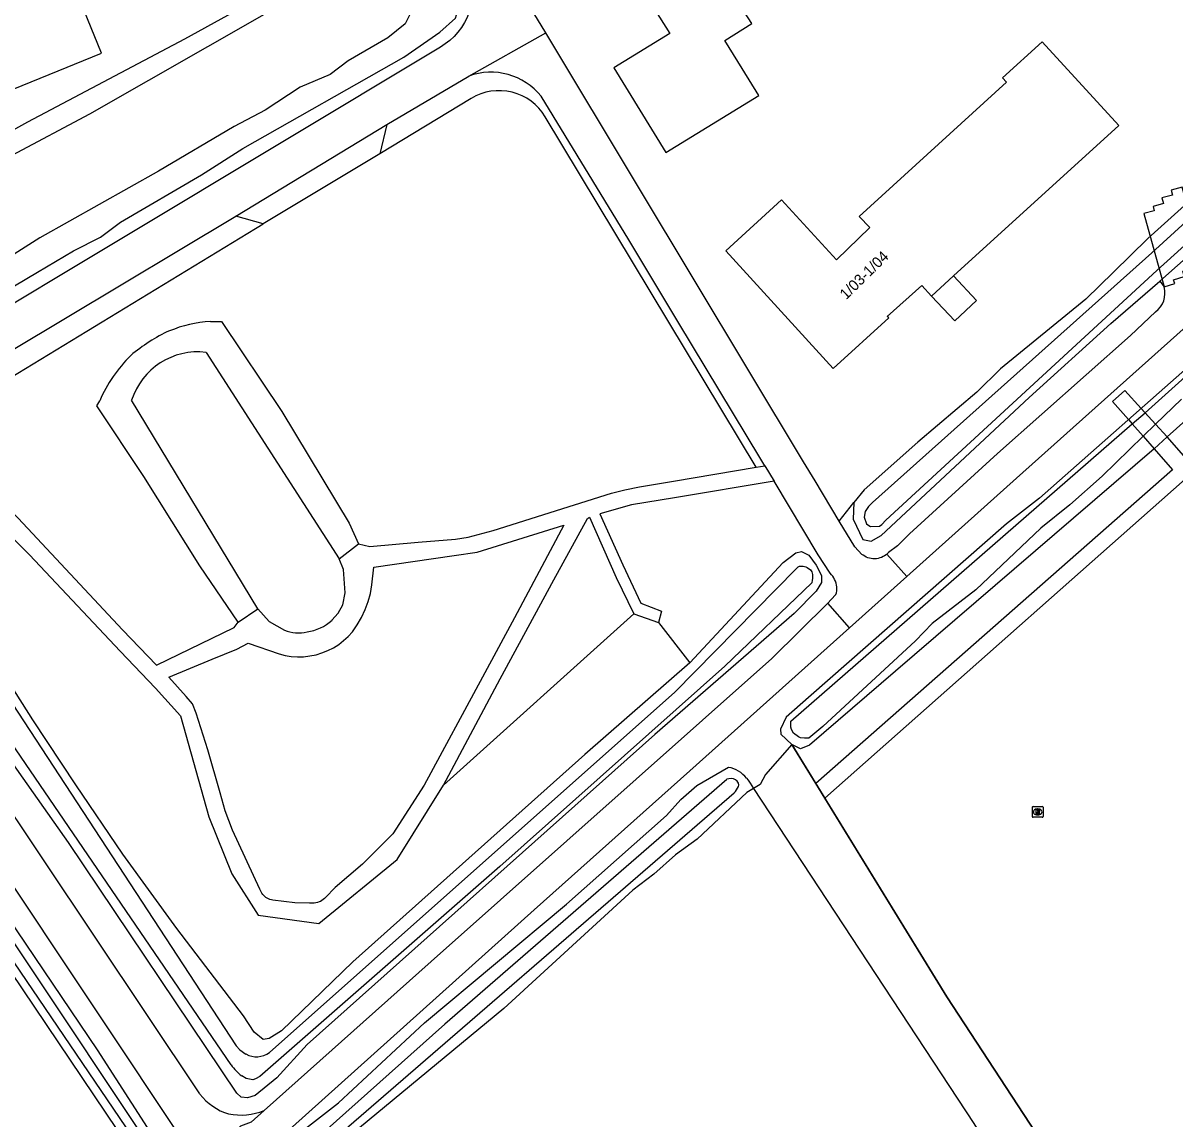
# Model space of a CAD drawing. Extents: x 162791 to 163827, y 385795 to 386523.
# Drawn here: x 163263.1 to 163370.1, y 386171.4 to 386273.1 of the extents above; entities that cross this region are included whole.
import ezdxf

# ---------------------------------------------------------------- set-up
doc = ezdxf.new("R2010")
doc.units = 0
for name, color, linetype in [('IMGEO_Dek', 7, 'Continuous'), ('IMGEO_Erf', 7, 'Continuous'), ('IMGEO_Gemengd_bos', 7, 'Continuous'), ('IMGEO_Grasland_overig', 7, 'Continuous'), ('IMGEO_Groenvoorziening', 7, 'Continuous'), ('IMGEO_Hek', 7, 'Continuous'), ('IMGEO_Meer_plas_ven_vijver', 7, 'Continuous'), ('IMGEO_Pand', 7, 'Continuous'), ('IMGEO_Pand_nummerreeks', 7, 'Continuous'), ('IMGEO_Parkeervlak_open', 7, 'Continuous'), ('IMGEO_Rijbaan_lokaal_gesloten', 7, 'Continuous'), ('IMGEO_Rijbaan_lokaal_onverhard', 7, 'Continuous'), ('IMGEO_Rijbaan_lokaal_open', 7, 'Continuous'), ('IMGEO_Rioolput', 7, 'Continuous'), ('IMGEO_Voetpad_halfverhard', 7, 'Continuous'), ('IMGEO_Voetpad_open', 7, 'Continuous'), ('IMGEO_Waterloop', 7, 'Continuous'), ('IMGEO_Woonerf_open', 7, 'Continuous')]:
    doc.layers.add(name, color=color, linetype=linetype)

msp = doc.modelspace()

# ---------------------------------------------------------------- linework, layer by layer
at = {"layer": 'IMGEO_Dek'}
for points in [[(163372.63, 386251.07), (163370.76, 386257.9), (163369.75, 386257.63), (163369.88, 386257.16), (163368.89, 386256.9), (163369.03, 386256.37), (163368.06, 386256.11), (163368.17, 386255.69), (163367.22, 386255.44), (163369.08, 386248.63), (163370.08, 386248.94), (163370.02, 386249.12), (163369.96, 386249.3), (163370.96, 386249.61), (163370.82, 386250.11), (163371.79, 386250.39), (163371.73, 386250.6), (163371.68, 386250.82)], [(163364.29, 386237.99), (163365.77, 386236.32), (163366.11, 386235.94), (163367.14, 386234.78), (163368.17, 386233.62), (163369.37, 386234.71), (163368.29, 386235.9), (163366.95, 386237.36), (163365.44, 386239.02)]]:
    msp.add_lwpolyline(points, close=True, dxfattribs=at)
at = {"layer": 'IMGEO_Erf'}
for points in [[(163358.27, 386329.73), (163369.6, 386309.18), (163388.13, 386275.57), (163388.75, 386273.87), (163388.79, 386272.87), (163388.39, 386271.95), (163377.29, 386261.58), (163375.71, 386260.44), (163370.68, 386255.93), (163367.59, 386253.14), (163364.39, 386250), (163361.83, 386247.49), (163353.89, 386241.04), (163351.71, 386238.86), (163346.21, 386234.23), (163341.23, 386229.79), (163340.29, 386228.61)], [(163276.83, 386311.46), (163279.76, 386304.64), (163280.52, 386303.16), (163282.08, 386299.04), (163282.71, 386297.57), (163284.13, 386298.22), (163285.26, 386295.57), (163283.84, 386294.94), (163285.21, 386290.76), (163289.29, 386279.83), (163289.57, 386278.55), (163289.29, 386277.99), (163288.89, 386277.59), (163278.14, 386271.64), (163263.57, 386263.94), (163238.52, 386250), (163202.05, 386229.7), (163201.46, 386229.64), (163200.89, 386229.9), (163200.49, 386230.52), (163192.64, 386244.3), (163191.66, 386246.6), (163189.98, 386249.35)], [(163274.97, 386170.16), (163270.07, 386177.82), (163239.23, 386223.44), (163238.43, 386224.34), (163237.21, 386225.02), (163236.42, 386225.12), (163236.06, 386224.76), (163236.06, 386224.12), (163236.48, 386222.54), (163248.69, 386204.78), (163271.93, 386170.32)]]:
    msp.add_lwpolyline(points, dxfattribs=at)
at = {"layer": 'IMGEO_Gemengd_bos'}
for points in [[(163304.75, 386266.14), (163296.27, 386260.98)], [(163331.22, 386231.89), (163311.63, 386264.44)], [(163254.1, 386235.44), (163285.45, 386254.48)], [(163280.54, 386245.44), (163281.58, 386245.44), (163287.17, 386237.08), (163293.43, 386226.72), (163294.29, 386224.79)], [(163283.13, 386217.51), (163279.55, 386222.75), (163274.35, 386231.03), (163270, 386237.61), (163270.26, 386238.07)], [(163325.04, 386213.73), (163315.3, 386205.22), (163293.77, 386185.98), (163287.15, 386179.57), (163285.99, 386178.87), (163285.43, 386178.77), (163284.59, 386179.47), (163283.61, 386180.97), (163277.41, 386189.09), (163272.42, 386195.99), (163268.06, 386202.41), (163264.06, 386208.45), (163254.95, 386222.79), (163250.27, 386230.43), (163248.69, 386232.43)], [(163302.17, 386202.38), (163319.84, 386218.29)], [(163322.14, 386217.49), (163325.04, 386213.73)]]:
    msp.add_lwpolyline(points, dxfattribs=at)
for centre, radius, start, end in [((163307.35, 386261.86), 5, 31.0344, 121.2892), ((163281.37, 386233.13), 12.33, 93.9007, 112.0819), ((163283.46, 386230.07), 15.98, 114.8683, 130.2264), ((163282.31, 386232.89), 13.11, 134.3562, 156.7334)]:
    msp.add_arc(centre, radius, start, end, dxfattribs=at)
at = {"layer": 'IMGEO_Grasland_overig'}
for points in [[(163334.51, 386206.17), (163332.07, 386203.39), (163331.59, 386202.45), (163330.97, 386202.08)], [(163336.75, 386202.54), (163334.51, 386206.17)], [(163330.97, 386202.08), (163351.42, 386170.99), (163365.11, 386149)], [(163362.1, 386162.58), (163348.93, 386182.75), (163337.58, 386201.19)]]:
    msp.add_lwpolyline(points, dxfattribs=at)
at = {"layer": 'IMGEO_Groenvoorziening'}
for points in [[(163368.7, 386249.16), (163371.96, 386252.09), (163377.03, 386256.71), (163385.29, 386263.34), (163391.11, 386268.71), (163392.33, 386269.57), (163393.55, 386270.85), (163394.31, 386272.69), (163394.11, 386273.91), (163392.21, 386278.19), (163380.4, 386298.93), (163365.93, 386326.24), (163364.85, 386327.62), (163362.85, 386330.8)], [(163252.47, 386242.88), (163264.5, 386250), (163267.84, 386251.98), (163270.34, 386253.26), (163272.2, 386254.66), (163279.7, 386259.03), (163283.55, 386261.5), (163298.51, 386269.95), (163301.83, 386272.3), (163303.3, 386273.58), (163303.68, 386274.82), (163303.11, 386277.82), (163302.56, 386279.48), (163300.7, 386283.62), (163296.46, 386294.57), (163295.4, 386296.91), (163293.61, 386299.37), (163293.55, 386299.51)], [(163427.28, 386208.26), (163414.75, 386232.44), (163403.01, 386252.5), (163398.12, 386260.39), (163369.37, 386234.71)], [(163340.29, 386228.61), (163340.21, 386227.08), (163341.13, 386225.2), (163341.89, 386225.04), (163342.83, 386225.55), (163356.55, 386238.38), (163364.15, 386245.23), (163368.7, 386249.16)], [(163368.7, 386249.16), (163369.08, 386248.63)], [(163372.59, 386242.33), (163357.51, 386229.03), (163354.47, 386226.65), (163336.07, 386210.51), (163333.99, 386208.69), (163333.47, 386207.59), (163333.51, 386207.13), (163334.51, 386206.17)], [(163368.17, 386233.62), (163344.16, 386212.98), (163336.15, 386206.1), (163335.32, 386205.75), (163334.51, 386206.17)], [(163338.93, 386226.9), (163340.29, 386228.61)], [(163325.04, 386213.73), (163333.73, 386223.04), (163334.91, 386223.94), (163335.43, 386224.08), (163336.11, 386223.72), (163336.79, 386222.82), (163337.29, 386221.84), (163337.29, 386221.2), (163336.79, 386220.4), (163334.73, 386218.32), (163321.8, 386207.09), (163289.51, 386178.31), (163286.71, 386175.23), (163284.71, 386173.57), (163283.97, 386173.37), (163283.41, 386173.43), (163282.99, 386173.79), (163267.36, 386197.05), (163261.24, 386205.77)], [(163287.36, 386166.66), (163287.39, 386168.29), (163287.86, 386169.13), (163288.55, 386169.85), (163292.44, 386172.89), (163300.42, 386180.32), (163313.6, 386191.33), (163322.88, 386199.58), (163324.21, 386201.04), (163325.71, 386202.34), (163328.64, 386204.04)], [(163330.33, 386203.03), (163330.48, 386202.84), (163330.67, 386202.56), (163330.97, 386202.08)], [(163330.97, 386202.08), (163330.35, 386201.71), (163325.73, 386197.38), (163323.73, 386195.92), (163321.71, 386194.12), (163319.76, 386192.64), (163307.78, 386181.66), (163290.44, 386167.33), (163290.58, 386166.67), (163292.7, 386163.19), (163298.6, 386154.45), (163302.55, 386148.89), (163315.83, 386127.93), (163319.34, 386122.66), (163322.46, 386118.35), (163322.79, 386117.68), (163363.42, 386149.31), (163364.28, 386149.43), (163365.11, 386149)]]:
    msp.add_lwpolyline(points, dxfattribs=at)
msp.add_arc((163328.15, 386201.32), 2.76, 38.0778, 79.7949, dxfattribs=at)
at = {"layer": 'IMGEO_Hek'}
for points in [[(163334.51, 386206.17), (163348.93, 386182.75), (163362.1, 386162.58)], [(163330.97, 386202.08), (163351.42, 386170.99), (163365.11, 386149)]]:
    msp.add_lwpolyline(points, dxfattribs=at)
at = {"layer": 'IMGEO_Meer_plas_ven_vijver'}
for points in [[(163280.15, 386242.56), (163292.5, 386223.4)], [(163284.93, 386218.74), (163273.23, 386238.11)]]:
    msp.add_lwpolyline(points, dxfattribs=at)
msp.add_arc((163279.38, 386236.15), 6.46, 83.1741, 162.3256, dxfattribs=at)
at = {"layer": 'IMGEO_Pand'}
for points in [[(163254.14, 386263.73), (163270.42, 386270.34), (163265.9, 386281.46), (163266.76, 386281.81), (163267.23, 386280.63), (163270.52, 386281.97), (163261.4, 386304.44), (163259.5, 386303.66), (163241.01, 386296.16)], [(163329.9, 386268.92), (163328.29, 386271.51), (163330.8, 386273.08), (163329.11, 386275.76), (163328.39, 386275.32), (163326.63, 386278.14), (163325.9, 386277.68), (163324.46, 386279.96), (163321.94, 386278.37), (163323.55, 386275.8), (163321.65, 386274.6), (163323.19, 386272.15), (163318, 386268.98), (163322.83, 386261.11), (163331.47, 386266.4), (163329.9, 386268.92)], [(163349.55, 386249.66), (163364.89, 386263.61), (163357.78, 386271.4), (163354.07, 386268.04), (163354.47, 386267.65), (163340.77, 386255.18), (163341.77, 386254.14), (163338.68, 386251.14), (163333.56, 386256.73), (163328.4, 386252), (163338.35, 386241.07), (163343.52, 386245.77), (163343.39, 386245.89), (163346.59, 386248.77), (163347.5, 386247.79)], [(163349.55, 386249.66), (163347.5, 386247.79)], [(163347.5, 386247.79), (163349.67, 386245.49), (163351.68, 386247.37), (163349.55, 386249.66)]]:
    msp.add_lwpolyline(points, dxfattribs=at)
at = {"layer": 'IMGEO_Parkeervlak_open'}
for points in [[(163282.9, 386255.22), (163296.91, 386263.73)], [(163296.91, 386263.73), (163296.27, 386260.98)], [(163296.27, 386260.98), (163285.45, 386254.48)], [(163285.45, 386254.48), (163282.9, 386255.22)]]:
    msp.add_lwpolyline(points, dxfattribs=at)
at = {"layer": 'IMGEO_Rijbaan_lokaal_gesloten'}
for points in [[(163369.08, 386248.63), (163370.08, 386248.94), (163370.02, 386249.12), (163369.96, 386249.3), (163370.96, 386249.61), (163370.82, 386250.11), (163371.79, 386250.39), (163371.73, 386250.6), (163371.68, 386250.82), (163372.63, 386251.07), (163373.14, 386251.61), (163373.59, 386251.78), (163375.27, 386252.83), (163375.62, 386252.47)], [(163377.43, 386250.6), (163374.94, 386248.38), (163355.39, 386230.89), (163345.19, 386221.76)], [(163368.3, 386246.33), (163365.96, 386244.13), (163353.63, 386233.16), (163345.45, 386225.73), (163344.35, 386224.61), (163343.51, 386223.98), (163343.39, 386223.87), (163343.34, 386223.83)], [(163345.19, 386221.76), (163343.34, 386223.83)], [(163337.86, 386219.29), (163332.67, 386214.15), (163301.05, 386186.01), (163285.54, 386172.19)], [(163339.87, 386217), (163337.86, 386219.29)], [(163286.36, 386169.05), (163288.16, 386170.66), (163310.61, 386190.82), (163325.04, 386203.73), (163339.87, 386217)], [(163285.54, 386172.19), (163284.33, 386171.11), (163283.34, 386170.74), (163279.05, 386166.85)]]:
    msp.add_lwpolyline(points, dxfattribs=at)
msp.add_arc((163367, 386248.06), 2.17, 306.9795, 15.362, dxfattribs=at)
at = {"layer": 'IMGEO_Rijbaan_lokaal_onverhard'}
for points in [[(163279.57, 386173.72), (163245.44, 386224.72)], [(163242.34, 386222.83), (163278.57, 386168.48)]]:
    msp.add_lwpolyline(points, dxfattribs=at)
for centre, radius, start, end in [((163283.65, 386176.76), 5.09, 216.7808, 253.8244), ((163283.37, 386177.46), 5.7, 258.3962, 292.3079)]:
    msp.add_arc(centre, radius, start, end, dxfattribs=at)
at = {"layer": 'IMGEO_Rijbaan_lokaal_open'}
for points in [[(163304.52, 386268.21), (163311.68, 386272.21)], [(163338.93, 386226.9), (163336.68, 386230.65), (163335.62, 386232.4), (163320.29, 386257.9), (163311.68, 386272.21)], [(163332.02, 386232.02), (163331.64, 386232.65), (163323.95, 386245.43), (163319.39, 386253.02), (163311.24, 386266.34)], [(163332.02, 386232.02), (163332.87, 386230.6)], [(163337.86, 386219.29), (163338.18, 386219.61), (163338.62, 386220.08), (163338.66, 386220.25), (163338.69, 386220.43), (163338.7, 386220.61), (163338.69, 386220.79), (163338.67, 386220.96), (163338.63, 386221.14), (163338.57, 386221.31), (163338.5, 386221.47), (163338.42, 386221.63), (163338.33, 386221.78), (163338.21, 386221.92), (163338.09, 386222.05), (163336.98, 386223.76), (163332.87, 386230.6)], [(163343.34, 386223.83), (163343.27, 386223.77), (163343.14, 386223.68), (163342.99, 386223.6), (163342.85, 386223.53), (163342.7, 386223.48), (163342.54, 386223.44), (163342.38, 386223.41), (163342.22, 386223.4), (163342.06, 386223.41), (163341.9, 386223.42), (163341.74, 386223.45), (163341.58, 386223.5), (163341.43, 386223.56), (163341.29, 386223.63), (163341.15, 386223.72), (163341.02, 386223.81), (163340.37, 386224.5), (163338.93, 386226.9)], [(163339.87, 386217), (163345.19, 386221.76)]]:
    msp.add_lwpolyline(points, dxfattribs=at)
msp.add_arc((163306.57, 386262.57), 6, 38.8826, 109.9355, dxfattribs=at)
at = {"layer": 'IMGEO_Rioolput'}
for p, q in [((163356.86, 386199.48), (163356.86, 386200.33)), ((163356.93, 386200.41), (163357.78, 386200.41)), ((163357.35, 386200.18), (163357.37, 386200.18)), ((163357.86, 386200.33), (163357.86, 386199.48)), ((163357.78, 386199.4), (163356.93, 386199.4)), ((163357.37, 386199.63), (163357.34, 386199.63))]:
    msp.add_line(p, q, dxfattribs=at)
for points in [[(163356.86, 386199.48), (163356.86, 386200.33)], [(163356.93, 386200.41), (163357.78, 386200.41)], [(163357.45, 386200.1), (163357.19, 386200.1), (163357.19, 386199.7)], [(163357.19, 386199.7), (163357.32, 386199.7), (163357.32, 386199.87), (163357.33, 386199.87)], [(163357.37, 386200.02), (163357.32, 386200.02), (163357.32, 386199.94)], [(163357.32, 386199.94), (163357.37, 386199.94)], [(163357.38, 386199.84), (163357.45, 386199.7), (163357.59, 386199.7), (163357.52, 386199.83)], [(163357.86, 386200.33), (163357.86, 386199.48)], [(163357.78, 386199.4), (163356.93, 386199.4)]]:
    msp.add_lwpolyline(points, dxfattribs=at)
for centre, radius, start, end in [((163356.93, 386200.33), 0.0765, 91.552, 178.448), ((163356.93, 386200.33), 0.0765, 91.552, 178.448), ((163357.33, 386199.81), 0.0533, 26.0293, 88.6989), ((163357.38, 386199.93), 0.0964, 77.0061, 93.1865), ((163357.35, 386200.13), 0.19, 274.7715, 282.9687), ((163357.39, 386199.98), 0.0378, 276.6634, 79.6772), ((163357.45, 386199.99), 0.109, 350.3612, 89.416), ((163357.44, 386199.99), 0.112, 277.5842, 350.9817), ((163357.43, 386199.78), 0.108, 29.5134, 73.7905), ((163357.78, 386200.33), 0.0765, 1.552, 88.448), ((163357.78, 386200.33), 0.0765, 1.552, 88.448), ((163356.93, 386199.48), 0.0765, 181.552, 268.448), ((163356.93, 386199.48), 0.0765, 181.552, 268.448), ((163357.78, 386199.48), 0.0765, 271.552, 358.448), ((163357.78, 386199.48), 0.0765, 271.552, 358.448)]:
    msp.add_arc(centre, radius, start, end, dxfattribs=at)
for centre, major_axis, ratio, start_param, end_param in [((163357.34, 386199.9), (-0.387, 0.002), 0.722429, 4.712389, 7.853982), ((163357.37, 386199.9), (-0.39, 0.002), 0.717154, 1.570796, 4.712389)]:
    msp.add_ellipse(centre, major_axis=major_axis, ratio=ratio, start_param=start_param, end_param=end_param, dxfattribs=at)
at = {"layer": 'IMGEO_Voetpad_halfverhard'}
for points in [[(163254.1, 386235.44), (163254.59, 386235), (163262.7, 386227.16), (163272.38, 386216.79), (163275.53, 386213.52), (163282.75, 386217.01), (163283.13, 386217.51)], [(163252.67, 386234.58), (163254.97, 386232.49), (163263.75, 386223.77), (163272.16, 386214.81), (163275.43, 386211.39), (163277.77, 386208.82), (163280.39, 386199.43), (163282.54, 386194.16), (163284.97, 386190.31), (163290.61, 386189.54), (163297.88, 386195.47), (163302.17, 386202.38)], [(163294.29, 386224.79), (163295.35, 386224.54), (163299.83, 386224.95), (163303.29, 386225.23), (163304.46, 386225.42), (163306.79, 386226.04), (163314.36, 386228.41), (163317.79, 386229.48), (163319.03, 386229.8), (163320.38, 386230.07), (163323.55, 386230.6), (163331.22, 386231.89)], [(163331.22, 386231.89), (163332.02, 386232.02)], [(163332.87, 386230.6), (163323.64, 386229.05), (163319.65, 386228.42), (163316.7, 386227.56), (163318.83, 386222.84), (163320.5, 386219.27), (163322.41, 386218.53), (163322.14, 386217.49)], [(163300.39, 386202.38), (163297.47, 386197.87), (163294.67, 386195.06), (163292.14, 386192.89), (163291.24, 386191.96), (163291.14, 386191.85), (163291.02, 386191.76), (163290.9, 386191.67), (163290.77, 386191.6), (163290.63, 386191.54), (163290.49, 386191.49), (163290.34, 386191.46), (163290.19, 386191.43), (163290.04, 386191.42), (163289.89, 386191.43), (163289.74, 386191.44), (163288.39, 386191.46), (163286.34, 386191.7), (163286.21, 386191.73), (163286.07, 386191.77), (163285.94, 386191.82), (163285.82, 386191.89), (163285.7, 386191.96), (163285.59, 386192.05), (163285.49, 386192.14), (163285.4, 386192.24), (163285.31, 386192.36), (163285.24, 386192.48), (163285.18, 386192.6), (163285.13, 386192.73), (163282.6, 386198.22), (163281.91, 386200), (163281.45, 386201.66), (163280.3, 386205.66), (163279.21, 386209.07), (163278.88, 386209.95), (163278.3, 386210.61), (163276.69, 386212.4), (163280.72, 386214.09), (163282.98, 386215.02), (163284.05, 386215.56), (163286.91, 386214.57), (163287.48, 386214.43), (163288.05, 386214.34), (163288.62, 386214.3), (163289.2, 386214.31), (163289.78, 386214.38), (163290.35, 386214.49), (163290.9, 386214.66), (163291.44, 386214.88), (163291.96, 386215.14), (163292.45, 386215.45), (163292.91, 386215.8), (163293.33, 386216.19), (163293.73, 386216.61), (163294.18, 386217.27), (163294.58, 386217.96), (163294.92, 386218.68), (163295.19, 386219.42), (163295.4, 386220.19), (163295.54, 386220.98), (163295.73, 386222.61), (163303.17, 386223.69), (163305.3, 386224), (163313.36, 386226.51), (163308.76, 386217.91), (163305.79, 386212.4), (163300.39, 386202.38)], [(163302.17, 386202.38), (163307.46, 386212.25), (163312.43, 386221.46), (163315.55, 386227.15), (163315.74, 386227.25), (163318.2, 386221.65), (163319.84, 386218.29)], [(163292.5, 386223.4), (163294.29, 386224.79)], [(163291.82, 386217.7), (163292.4, 386218.36), (163292.83, 386219.12), (163293.06, 386220.23), (163292.89, 386222.41), (163292.5, 386223.4)], [(163283.13, 386217.51), (163284.93, 386218.74)], [(163284.93, 386218.74), (163286, 386217.57), (163287.41, 386216.78)], [(163319.84, 386218.29), (163322.14, 386217.49)]]:
    msp.add_lwpolyline(points, dxfattribs=at)
for centre, radius, start, end in [((163288.92, 386220.92), 4.35, 278.0002, 312.0036), ((163288.71, 386219.91), 3.39, 247.4748, 283.8564)]:
    msp.add_arc(centre, radius, start, end, dxfattribs=at)
at = {"layer": 'IMGEO_Voetpad_open'}
for points in [[(163372.63, 386251.07), (163370.76, 386257.9), (163369.75, 386257.63), (163369.88, 386257.16), (163368.89, 386256.9), (163369.03, 386256.37), (163368.06, 386256.11), (163368.17, 386255.69), (163367.22, 386255.44), (163369.08, 386248.63), (163370.08, 386248.94), (163370.02, 386249.12), (163369.96, 386249.3), (163370.96, 386249.61), (163370.82, 386250.11), (163371.79, 386250.39), (163371.73, 386250.6), (163371.68, 386250.82), (163372.63, 386251.07)], [(163365.44, 386239.02), (163364.29, 386237.99), (163365.77, 386236.32), (163366.11, 386235.94), (163367.14, 386234.78), (163368.17, 386233.62), (163369.37, 386234.71), (163368.29, 386235.9), (163367.32, 386236.95), (163366.95, 386237.36), (163365.44, 386239.02)], [(163337.58, 386201.19), (163375.63, 386234.85), (163374.7, 386235.79), (163371.15, 386232.71), (163369.37, 386234.71)], [(163369.37, 386234.71), (163368.17, 386233.62)], [(163368.17, 386233.62), (163369.86, 386231.66), (163336.75, 386202.54)], [(163337.58, 386201.19), (163336.75, 386202.54)]]:
    msp.add_lwpolyline(points, dxfattribs=at)
at = {"layer": 'IMGEO_Waterloop'}
for points in [[(163262.13, 386260.88), (163269.34, 386264.69), (163291.27, 386277.25), (163291.53, 386278.53), (163291.33, 386279.8), (163290.03, 386283.66), (163289.41, 386284.9), (163286.87, 386291.58), (163285.47, 386295.67), (163284.47, 386298.38), (163278.52, 386313.1), (163278.21, 386313.61), (163277.03, 386314.34), (163275.95, 386314.7), (163274.89, 386314.47), (163271.39, 386312.98)], [(163299.41, 386274.6), (163298.63, 386273.05), (163297.01, 386271.77), (163293.33, 386269.61), (163291.67, 386268.37), (163288.89, 386267.18), (163285.63, 386265.04), (163282.76, 386263.54), (163275.72, 386259.39), (163264.7, 386253.2), (163259.65, 386250)], [(163371.1, 386254.68), (163367.96, 386251.8), (163342.03, 386228.61), (163341.64, 386228.24), (163341.34, 386227.79), (163341.24, 386227.25), (163341.46, 386226.64), (163341.58, 386226.54), (163341.83, 386226.41), (163342.65, 386226.44), (163342.89, 386226.59), (163343.26, 386226.97), (163368.42, 386250.15), (163371.63, 386253.08)], [(163370.69, 386238.23), (163368.29, 386235.9), (163367.14, 386234.78), (163363.35, 386231.08), (163360.35, 386228.41), (163357.63, 386226.25), (163351.61, 386220.53), (163347.57, 386217.4), (163346.01, 386215.78), (163337.41, 386207.83), (163336.09, 386206.75), (163335.7, 386206.74), (163335.32, 386206.79), (163335.13, 386206.86), (163334.68, 386207.22), (163334.48, 386207.56), (163334.43, 386207.76), (163334.43, 386208.32), (163366.11, 386235.94), (163367.32, 386236.95), (163379.1, 386247.54)], [(163282.46, 386176.42), (163246.5, 386229.06), (163246.53, 386230.33), (163246.84, 386230.78), (163247.84, 386231.17), (163248.64, 386230.86), (163252.8, 386224.21), (163282.93, 386178.18)], [(163237.48, 386222.5), (163237.35, 386222.72), (163237.3, 386222.9), (163237.35, 386223.22), (163237.48, 386223.45), (163237.62, 386223.57), (163237.92, 386223.64), (163238.44, 386223.52), (163275.25, 386168.27), (163275.18, 386166.43), (163274.92, 386166.02), (163274.67, 386165.69), (163273.71, 386164.82), (163272.34, 386163.57), (163235.78, 386130.19), (163234.78, 386129.26), (163230.58, 386125.39), (163228.62, 386123.58)], [(163227.42, 386124.6), (163230.07, 386127.03), (163230.82, 386127.65), (163233.56, 386130.11), (163233.95, 386130.45), (163240.94, 386136.66), (163273.9, 386166.17), (163274.36, 386166.68), (163274.54, 386167.36), (163274.4, 386168.21), (163273.87, 386168.93), (163237.48, 386222.5)], [(163286.03, 386177.57), (163323.67, 386211.02), (163334.93, 386222.48), (163335.12, 386222.65), (163335.23, 386222.7), (163335.58, 386222.72), (163335.83, 386222.64), (163335.96, 386222.58), (163336.27, 386222.38), (163336.39, 386222.18), (163336.45, 386221.93), (163336.44, 386221.56), (163336.42, 386221.42), (163336.37, 386221.18), (163328.29, 386213.44), (163307.42, 386194.84), (163285.14, 386175.33), (163284.72, 386175.11), (163284.47, 386175.04), (163283.86, 386175.14), (163283.45, 386175.4)], [(163328.49, 386202.92), (163302.32, 386180.19), (163289.08, 386168.41), (163288.88, 386168.13), (163288.7, 386167.86), (163288.6, 386167.63), (163288.54, 386167.26)], [(163329.56, 386202.24), (163329.6, 386202.42), (163329.58, 386202.58), (163329.46, 386202.76), (163329.29, 386202.89)], [(163289.61, 386167.33), (163289.68, 386167.45), (163289.81, 386167.61), (163289.95, 386167.77), (163329.17, 386201.68)], [(163282.93, 386178.18), (163283.28, 386177.83), (163283.83, 386177.42)]]:
    msp.add_lwpolyline(points, dxfattribs=at)
for centre, radius, start, end in [((163328.85, 386201.94), 1.05, 65.1783, 109.9484), ((163327.71, 386203.1), 2.04, 315.9994, 335.2691), ((163284.82, 386179.18), 2.01, 240.5307, 306.9591), ((163286.59, 386179.41), 5.1, 215.9692, 231.9746)]:
    msp.add_arc(centre, radius, start, end, dxfattribs=at)
at = {"layer": 'IMGEO_Woonerf_open'}
for points in [[(163296.14, 386299.05), (163304.41, 386278.88), (163304.6, 386278.38), (163304.76, 386277.87), (163304.87, 386277.34), (163304.93, 386276.81), (163304.95, 386276.27), (163304.93, 386275.73), (163304.86, 386275.2), (163304.74, 386274.67), (163304.58, 386274.16), (163304.37, 386273.66), (163304.13, 386273.18), (163303.84, 386272.73), (163303.52, 386272.29), (163303.16, 386271.89), (163302.77, 386271.52), (163302.35, 386271.19), (163301.9, 386270.89), (163227.75, 386226.41)], [(163311.68, 386272.21), (163310.57, 386274.05)], [(163296.91, 386263.73), (163304.52, 386268.21)], [(163252.17, 386236.84), (163267.08, 386245.73), (163282.9, 386255.22)]]:
    msp.add_lwpolyline(points, dxfattribs=at)

# ---------------------------------------------------------------- texts
at = {"layer": 'IMGEO_Pand_nummerreeks'}
msp.add_text('1/03-1/04', height=1, rotation=44.387, dxfattribs=at).set_placement((163339.56, 386247.4))

doc.saveas('drawing.dxf')
